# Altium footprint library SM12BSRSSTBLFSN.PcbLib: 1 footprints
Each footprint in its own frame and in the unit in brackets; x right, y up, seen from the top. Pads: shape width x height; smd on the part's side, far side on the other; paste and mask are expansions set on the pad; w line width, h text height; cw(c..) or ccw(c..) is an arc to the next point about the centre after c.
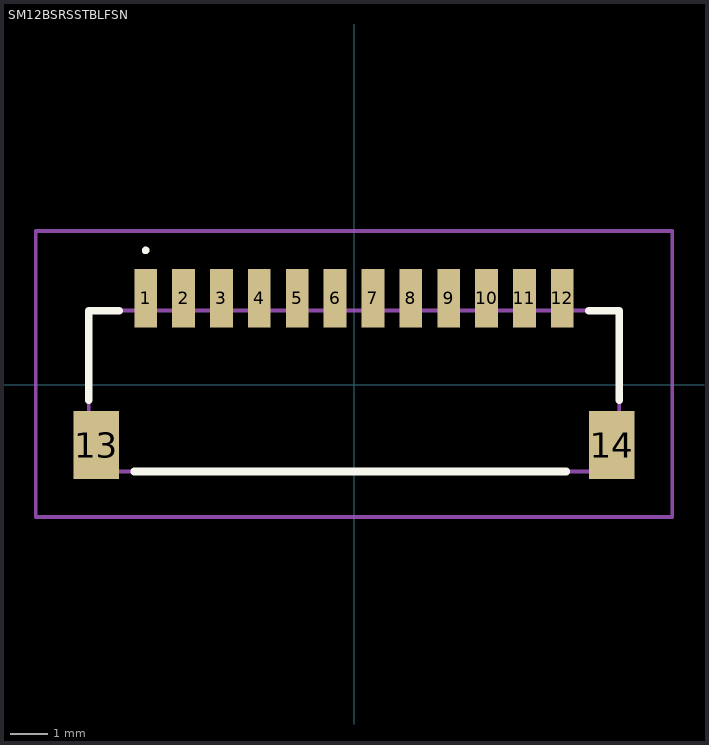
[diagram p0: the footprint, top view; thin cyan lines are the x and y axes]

## SM12BSRSSTBLFSN [mm]
pads (14):
  rect 0.6x1.55 smd: 1(-5.5,2.287) 2(-4.5,2.287) 3(-3.5,2.287) 4(-2.5,2.287) 5(-1.5,2.287) 6(-0.5,2.287) 7(0.5,2.287) 8(1.5,2.287) 9(2.5,2.287) 10(3.5,2.287) 11(4.5,2.287) 12(5.5,2.287)
  rect 1.2x1.8 smd: 13(-6.8,-1.588) 14(6.8,-1.588)
Top Overlay:
  lines w0.1: -5.5,3.5 cw(c-5.5,3.55) -5.5,3.6 ; -5.5,3.5 -5.5,3.5 ; -5.5,3.5 ccw(c-5.5,3.55) -5.5,3.6 ; -5.5,3.6 -5.5,3.6
  lines w0.2: -7,-0.4 -7,1.962 -6.2,1.962 ; -5.8,-2.288 5.6,-2.288 ; 6.2,1.962 7,1.962 7,-0.4
Mechanical 15:
  lines w0.1: -7,-2.288 7,-2.288 7,1.962 -7,1.962 -7,-2.288
Mechanical 20:
  lines w0.1: -8.4,-3.488 8.4,-3.488 8.4,4.062 -8.4,4.062 -8.4,-3.488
